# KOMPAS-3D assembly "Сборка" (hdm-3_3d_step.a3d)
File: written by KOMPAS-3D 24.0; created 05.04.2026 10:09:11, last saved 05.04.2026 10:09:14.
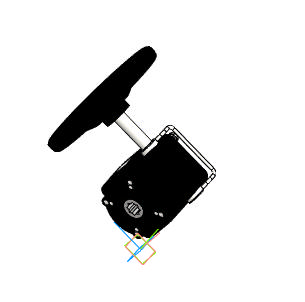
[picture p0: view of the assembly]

Document properties: Автор: R2D2; Полное имя файла: E:\Работа\Зайцев\Аксессуары для пневмоприводов\Ручной дублер DN.ru\MON3-700-T38-ISO Ручной дублер DN.ru\исходные материалы\hdm-3_3d_step.a3d

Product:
- Component [detail]: Деталь1  | qty 1  | Масса: 21.052029; Автор: R2D2; source file: Деталь1 Деталь1.m3d
- Component [detail]: Деталь 2  | qty 1  | Масса: 6.045553; Автор: R2D2; source file: Деталь 2 Деталь 2.m3d
- Component [detail]: AS 1427 - M8 x 12(4)  | designation AS 1427 - M8 x 12  | qty 1  | Масса: 0.011976; Автор: R2D2; source file: AS 1427 - M8 x 12 AS 1427 - M8 x 12(4).m3d
- Component [detail]: AS 1427 - M8 x 12(4)  | designation AS 1427 - M8 x 12  | qty 3  | Масса: 0.011976; Комментарий: Винты мелкие крепежные   метрические ISO; Автор: R2D2; additional columns: Сталь, мягкая; source file: AS 1427 - M8 x 12 AS 1427 - M8 x 12(4).m3d
- Component [detail]: AS 1420 - 1973 - M6 x 10  | qty 1  | Масса: 0.00526; Автор: R2D2; source file: AS 1420 - 1973 - M6 x 10 AS 1420 - 1973 - M6 x 10.m3d
- Part/product: Сборка
    Масса: 27.150746

Referenced files in E:\Работа\Зайцев\Аксессуары для пневмоприводов\Ручной дублер DN.ru\MON3-700-T38-ISO Ручной дублер DN.ru\исходные материалы\: Деталь1 Деталь1.m3d, Деталь 2 Деталь 2.m3d, AS 1427 - M8 x 12 AS 1427 - M8 x 12(4).m3d, AS 1420 - 1973 - M6 x 10 AS 1420 - 1973 - M6 x 10.m3d
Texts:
  Деталь1 Деталь1
  Деталь 2 Деталь 2
  AS 1427 - M8 x 12 AS 1427 - M8 x 12(4) (1)
  AS 1427 - M8 x 12 AS 1427 - M8 x 12(4) (2)
  AS 1427 - M8 x 12 AS 1427 - M8 x 12(4) (3)
  AS 1427 - M8 x 12 AS 1427 - M8 x 12(4) (4)
  AS 1420 - 1973 - M6 x 10 AS 1420 - 1973 - M6 x 10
